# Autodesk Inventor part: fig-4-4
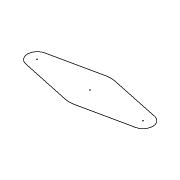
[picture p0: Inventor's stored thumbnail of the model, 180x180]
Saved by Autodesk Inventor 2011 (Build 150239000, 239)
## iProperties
Created: 2005-02
Part Number: fig-4-4
Document SubType Name: Modeling
Designer: CADCIM
Manufacturer: Standard
Standards Organization: Custom
Density: 1 g/cm^3
Author: CADCIM
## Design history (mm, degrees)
sketch "Sketch1"
  geometry: L1 (-33.874, 5.844)-(-2.722, 12.469); L2 (2.595, 12.472)-(33.871, 5.852); L3 (-33.884, -5.902)-(-2.745, -12.585); L4 (2.595, -12.592)-(33.871, -5.972); A1 r 6.006 centre (-32.624, -0.03) between (-33.874, 5.844) and (-33.884, -5.902); A2 r 6.043 centre (32.619, -0.06) between (33.871, -5.972) and (33.871, 5.852); A3 r 12.81 centre (-0.057, -0.06) between (-2.745, -12.585) and (2.595, -12.592); A4 r 12.81 centre (-0.057, -0.06) between (2.595, 12.472) and (-2.722, 12.469)
  constraints: 8 end point, 8 point on circle, 8 tangent, 4 centre point, 1 other
